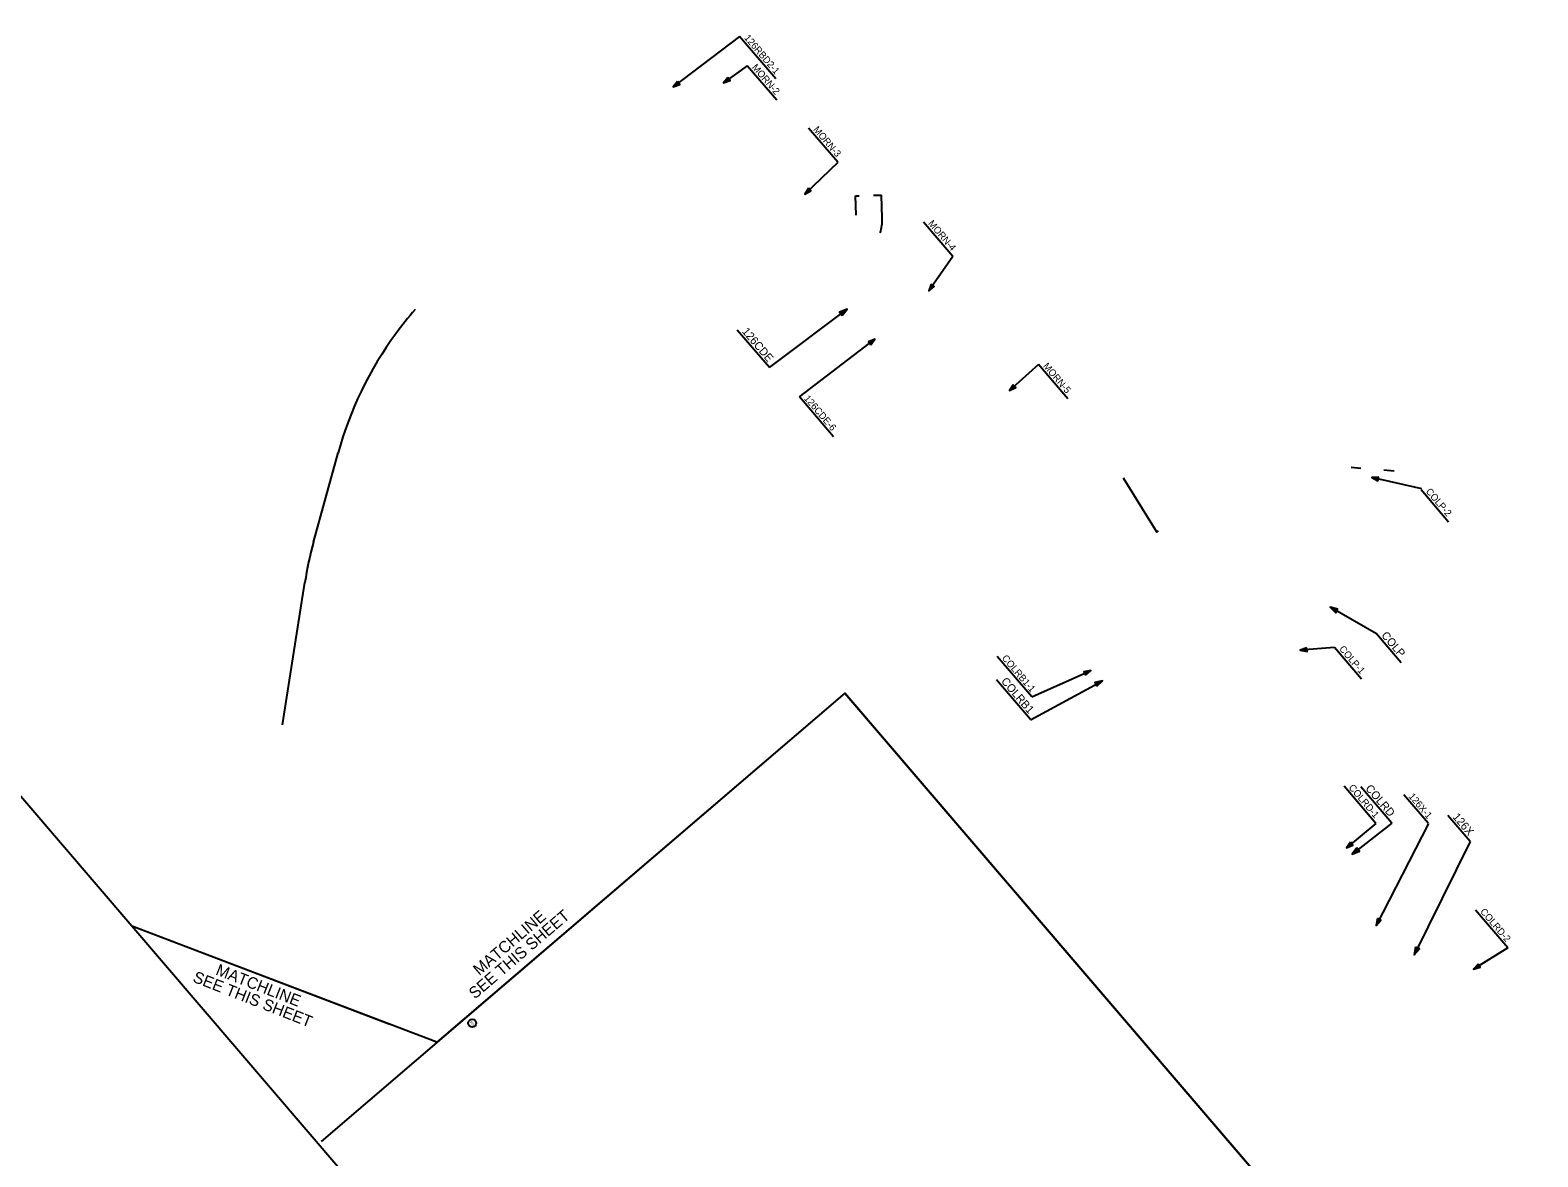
# Model space of a CAD drawing. Extents: x 1941897 to 1978064, y 805467 to 836604.
# Drawn here: x 1956688 to 1961909, y 813509 to 817410 of the extents above; entities that cross this region are included whole.
import ezdxf

# ---------------------------------------------------------------- set-up
doc = ezdxf.new("R2010")
doc.units = 0
for name, color, linetype in [('RD_EX_DV_TX_Prop', 7, 'Continuous'), ('RD_EX_H20_TX', 7, 'Continuous'), ('RD_PD_RW', 7, 'Continuous'), ('RD_SHT_Bndy', 7, 'Continuous'), ('RD_SHT_MatchLine', 7, 'Continuous'), ('RD_SHT_TX', 7, 'Continuous'), ('RD_TX_RoadID', 7, 'Continuous')]:
    doc.layers.add(name, color=color, linetype=linetype)

msp = doc.modelspace()

# ---------------------------------------------------------------- linework, layer by layer
at = {"layer": 'RD_EX_DV_TX_Prop'}
msp.add_circle((1958218.9, 813971.3), 13.8, dxfattribs=at)
at = {"layer": 'RD_EX_H20_TX'}
for points in [[(1963151.2, 810860.3), (1959509.3, 815114.3), (1958096.8, 813905.1), (1957040.5, 814307.7), (1947588.1, 825348.6), (1952108, 829218.2), (1965848, 813169.1)], [(1963151.2, 810860.3), (1959509.3, 815114.3), (1958096.8, 813905.1), (1957040.5, 814307.7), (1947588.1, 825348.6), (1952108, 829218.2), (1965848, 813169.1)], [(1963151.2, 810860.3), (1959509.3, 815114.3), (1958096.8, 813905.1), (1957040.5, 814307.7), (1947588.1, 825348.6), (1952108, 829218.2), (1965848, 813169.1)], [(1963151.2, 810860.3), (1959509.3, 815114.3), (1958096.8, 813905.1), (1957040.5, 814307.7), (1949323.3, 823321.8), (1953668.8, 827395), (1965848, 813169.1)], [(1963151.2, 810860.3), (1959509.3, 815114.3), (1958096.8, 813905.1), (1957040.5, 814307.7), (1949323.3, 823321.8), (1953668.8, 827395), (1965848, 813169.1)], [(1963151.2, 810860.3), (1959509.3, 815114.3), (1958096.8, 813905.1), (1957040.5, 814307.7), (1949323.3, 823321.8), (1953668.8, 827395), (1965848, 813169.1)]]:
    msp.add_lwpolyline(points, close=True, dxfattribs=at)
at = {"layer": 'RD_PD_RW'}
for p, q in [((1959546, 816835.8), (1959558.7, 816836.2)), ((1959548.5, 816769.6), (1959546, 816835.8)), ((1959608.7, 816838.1), (1959636, 816839.2)), ((1959639, 816759), (1959636, 816839.2)), ((1957669.5, 815637.6), (1957754.3, 815946)), ((1961262.4, 815896.3), (1961296.5, 815893.2)), ((1961411.8, 815882.9), (1961376.2, 815886.1)), ((1960473.2, 815859.7), (1960589.4, 815671.7)), ((1960589.4, 815671.7), (1960595.9, 815676.4)), ((1957562.4, 815004), (1957639.3, 815497.1))]:
    msp.add_line(p, q, dxfattribs=at)
for centre, radius, start, end in [((1959494.1, 816753.5), 145, 341.7031, 2.1782), ((1958975, 815610.3), 1266, 138.9015, 143.7455), ((1958975, 815610.3), 1266, 143.7456, 164.6268), ((1958890.2, 815302), 1266, 164.6268, 171.1348)]:
    msp.add_arc(centre, radius, start, end, dxfattribs=at)
at = {"layer": 'RD_SHT_Bndy'}
msp.add_lwpolyline([(1946512.2, 824990.8), (1956970, 812775.5), (1957767.7, 813458.3), (1947309.9, 825673.6)], close=True, dxfattribs=at)
at = {"layer": 'RD_SHT_MatchLine'}
for p, q in [((1959509.3, 815114.3), (1957695.2, 813561.2)), ((1959509.3, 815114.3), (1963151.2, 810860.3)), ((1957933.9, 813967.1), (1957043.6, 814306.5))]:
    msp.add_line(p, q, dxfattribs=at)
at = {"layer": 'RD_TX_RoadID'}
for p, q in [((1959270.4, 817241.6), (1959144.6, 817388.5)), ((1959273.2, 817167.8), (1959171.6, 817286.5)), ((1959485.1, 816952.5), (1959383.7, 817070.9)), ((1959883.5, 816626.7), (1959781.6, 816745.6)), ((1959248, 816241.9), (1959136.8, 816371.7)), ((1960281.4, 816133), (1960179.6, 816251.9)), ((1959469.8, 816002.2), (1959351.9, 816139.9)), ((1961600.3, 815706.6), (1961505, 815817.9)), ((1961436.3, 815219.4), (1961350.9, 815319.2)), ((1961299.1, 815162.7), (1961205.2, 815272.5)), ((1960156.5, 815101.2), (1960037.1, 815240.7)), ((1960152.1, 815022.7), (1960034.3, 815160.4)), ((1961348.5, 814663.4), (1961238, 814792.4)), ((1961403.7, 814663.5), (1961296, 814789.4)), ((1961529.3, 814663.9), (1961445.6, 814761.7)), ((1961675.1, 814600.1), (1961597.7, 814690.6)), ((1961805.4, 814232.3), (1961693.5, 814363))]:
    msp.add_line(p, q, dxfattribs=at)
for points in [[(1959145, 817388), (1958915.1, 817213.3)], [(1959171.6, 817286.5), (1959089.3, 817227.2)], [(1959485.5, 816952), (1959370.9, 816842.6)], [(1959883.5, 816626.7), (1959800.2, 816507.4)], [(1959248, 816241.9), (1959516.9, 816444.4)], [(1959351.9, 816139.9), (1959613.7, 816339.9)], [(1960179.6, 816251.9), (1960079.6, 816162.2)], [(1961507, 815821.2), (1961334.1, 815860.8)], [(1961350.9, 815319.2), (1961189.5, 815411.7)], [(1961205.2, 815272.5), (1961086.6, 815262.6)], [(1960152.1, 815022.2), (1960402.1, 815157.2)], [(1960156.5, 815101.2), (1960361.1, 815192.1)], [(1961348.5, 814663.4), (1961246.6, 814578.1)], [(1961403.7, 814663.5), (1961265.9, 814556.2)], [(1961530.1, 814663), (1961349.1, 814310)], [(1961675.1, 814600.1), (1961480.5, 814207.7)], [(1961805.6, 814232), (1961686.6, 814158.8)]]:
    msp.add_lwpolyline(points, dxfattribs=at)
for points in [[(1959104.5, 817245.8), (1959089.3, 817227.2), (1959111.7, 817235.7)], [(1958929.8, 817232.3), (1958915.1, 817213.3), (1958937.3, 817222.4)], [(1959383.4, 816863.1), (1959370.9, 816842.6), (1959392, 816854.1)], [(1959808.4, 816529.9), (1959800.2, 816507.4), (1959818.6, 816522.8)], [(1959499.6, 816422.3), (1959516.9, 816444.4), (1959490.9, 816433.9)], [(1959599, 816320.9), (1959613.7, 816339.9), (1959591.5, 816330.8)], [(1960092.7, 816182.3), (1960079.6, 816162.2), (1960101, 816173.1)], [(1961358.1, 815861.7), (1961334.1, 815860.8), (1961355.3, 815849.6)], [(1961216.5, 815404.6), (1961189.5, 815411.7), (1961209.3, 815392)], [(1961109.2, 815270.7), (1961086.6, 815262.6), (1961110.2, 815258.3)], [(1960342.4, 815177), (1960361.1, 815192.1), (1960337.4, 815188.3)], [(1960381.8, 815138), (1960402.1, 815157.2), (1960374.9, 815150.7)], [(1961260.4, 814597.8), (1961246.6, 814578.1), (1961268.4, 814588.2)], [(1961282.8, 814578.5), (1961265.9, 814556.2), (1961291.7, 814567.1)], [(1961354.1, 814333.5), (1961349.1, 814310), (1961365.2, 814327.8)], [(1961486, 814235.2), (1961480.5, 814207.7), (1961499, 814228.7)], [(1961703.1, 814176.2), (1961686.6, 814158.8), (1961709.6, 814165.6)]]:
    msp.add_lwpolyline(points, close=True, dxfattribs=at)

# ---------------------------------------------------------------- texts
at = {"layer": 'RD_EX_DV_TX_Prop'}
msp.add_text('515', height=8, rotation=311.7715, dxfattribs=at).set_placement((1958210.1, 813975.1))
at = {"layer": 'RD_SHT_TX'}
for s, rotation, p in [('SEE THIS SHEET', 40.5675, (1958228.2, 814053)), ('MATCHLINE', 40.5675, (1958243.3, 814134.5)), ('MATCHLINE', 338.5675, (1957327.6, 814140.6)), ('SEE THIS SHEET', 338.5675, (1957248.5, 814115.7))]:
    msp.add_text(s, height=40, rotation=rotation, dxfattribs=at).set_placement(p)
at = {"layer": 'RD_TX_RoadID'}
for s, height, p in [('126RBD2-1', 24, (1959159, 817382.4)), ('MORN-2', 24, (1959186, 817280.4)), ('MORN-3', 24, (1959398.2, 817064.8)), ('MORN-4', 24, (1959796.1, 816739.5)), ('126CDE', 28, (1959151.3, 816365.6)), ('MORN-5', 24, (1960194, 816245.8)), ('126CDE-6', 24, (1959366.3, 816133.8)), ('COLP-2', 24, (1961519.4, 815811.8)), ('COLP', 28, (1961365.3, 815313.2)), ('COLP-1', 24, (1961219.6, 815266.4)), ('COLRB1-1', 24, (1960051.5, 815234.6)), ('COLRB1', 28, (1960048.7, 815154.3)), ('COLRD-1', 24, (1961252.4, 814786.4)), ('COLRD', 28, (1961310.4, 814783.3)), ('126X-1', 24, (1961460, 814755.6)), ('126X', 28, (1961612.1, 814684.6)), ('COLRD-2', 24, (1961707.9, 814356.9))]:
    msp.add_text(s, height=height, rotation=310.5675, dxfattribs=at).set_placement(p)

doc.saveas('drawing.dxf')
